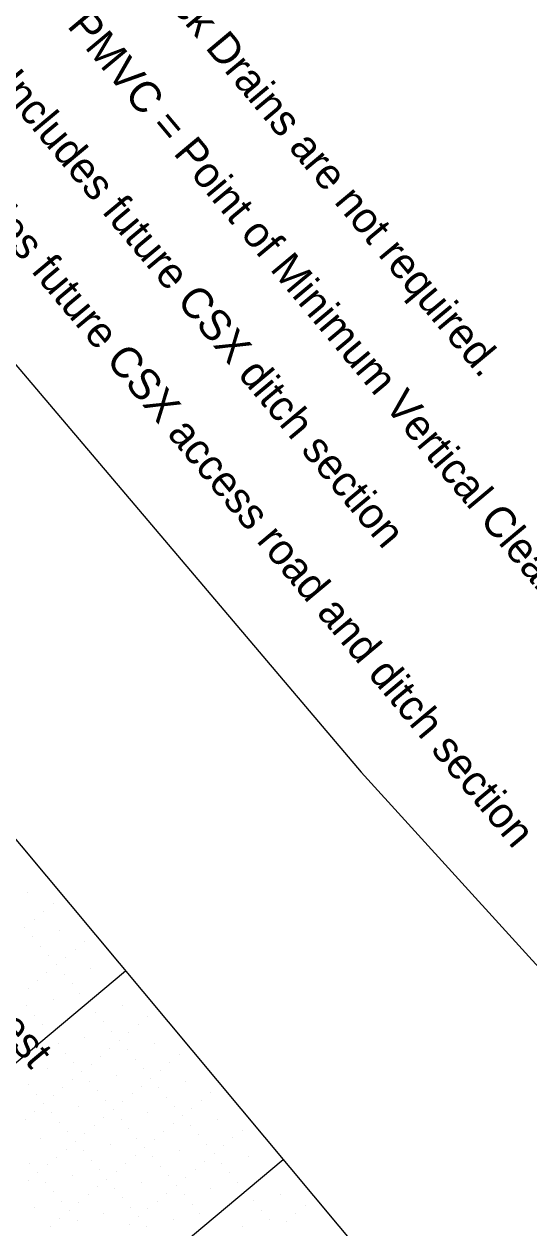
# Model space of a CAD drawing. Extents: x 2042995 to 2043795, y 305365 to 306249.
# Drawn here: x 2043570.9 to 2043611.9, y 305582.4 to 305680.3 of the extents above; entities that cross this region are included whole.
import ezdxf

# ---------------------------------------------------------------- set-up
doc = ezdxf.new("R2010")
doc.units = 0
for name, color, linetype in [('BR_AUTO DIMENSION', 7, 'Continuous'), ('BR_BORDER LINES', 7, 'Continuous'), ('BR_GRID DOTS', 7, 'Continuous'), ('BR_GRID LINES', 7, 'Continuous'), ('BR_GROUND LINES', 7, 'Continuous'), ('BR_TEXT', 7, 'Continuous')]:
    doc.layers.add(name, color=color, linetype=linetype)

msp = doc.modelspace()

# ---------------------------------------------------------------- linework, layer by layer
at = {"layer": 'BR_BORDER LINES'}
msp.add_line((2043183.839, 306076.621), (2043615.462, 305559.826), dxfattribs=at)
at = {"layer": 'BR_GRID DOTS'}
for p, q in [((2043571.193, 305609.711), (2043571.193, 305609.711)), ((2043573.243, 305608.817), (2043573.243, 305608.817)), ((2043571.708, 305607.535), (2043571.708, 305607.535)), ((2043572.475, 305608.176), (2043572.475, 305608.176)), ((2043570.94, 305606.894), (2043570.94, 305606.894)), ((2043573.757, 305606.641), (2043573.757, 305606.641)), ((2043571.581, 305606.126), (2043571.581, 305606.126)), ((2043575.807, 305605.747), (2043575.807, 305605.747)), ((2043572.222, 305605.359), (2043572.222, 305605.359)), ((2043572.863, 305604.591), (2043572.863, 305604.591)), ((2043575.039, 305605.106), (2043575.039, 305605.106)), ((2043573.504, 305603.824), (2043573.504, 305603.824)), ((2043574.272, 305604.465), (2043574.272, 305604.465)), ((2043576.321, 305603.571), (2043576.321, 305603.571)), ((2043571.969, 305602.542), (2043571.969, 305602.542)), ((2043572.737, 305603.183), (2043572.737, 305603.183)), ((2043574.145, 305603.056), (2043574.145, 305603.056)), ((2043571.202, 305601.901), (2043571.202, 305601.901)), ((2043574.786, 305602.289), (2043574.786, 305602.289)), ((2043573.251, 305601.007), (2043573.251, 305601.007)), ((2043575.427, 305601.521), (2043575.427, 305601.521)), ((2043571.075, 305600.492), (2043571.075, 305600.492)), ((2043571.716, 305599.725), (2043571.716, 305599.725)), ((2043576.709, 305599.986), (2043576.709, 305599.986)), ((2043578.885, 305600.501), (2043578.885, 305600.501)), ((2043580.935, 305599.607), (2043580.935, 305599.607)), ((2043572.357, 305598.957), (2043572.357, 305598.957)), ((2043577.35, 305599.219), (2043577.35, 305599.219)), ((2043580.167, 305598.966), (2043580.167, 305598.966)), ((2043575.815, 305597.937), (2043575.815, 305597.937)), ((2043577.991, 305598.451), (2043577.991, 305598.451)), ((2043578.632, 305597.684), (2043578.632, 305597.684)), ((2043579.4, 305598.325), (2043579.4, 305598.325)), ((2043573.639, 305597.422), (2043573.639, 305597.422)), ((2043574.28, 305596.655), (2043574.28, 305596.655)), ((2043577.865, 305597.043), (2043577.865, 305597.043)), ((2043579.273, 305596.916), (2043579.273, 305596.916)), ((2043581.449, 305597.431), (2043581.449, 305597.431)), ((2043574.921, 305595.887), (2043574.921, 305595.887)), ((2043576.33, 305595.761), (2043576.33, 305595.761)), ((2043577.097, 305596.402), (2043577.097, 305596.402)), ((2043579.914, 305596.149), (2043579.914, 305596.149)), ((2043582.732, 305595.896), (2043582.732, 305595.896)), ((2043583.499, 305596.537), (2043583.499, 305596.537)), ((2043572.745, 305595.373), (2043572.745, 305595.373)), ((2043575.562, 305595.12), (2043575.562, 305595.12)), ((2043578.379, 305594.867), (2043578.379, 305594.867)), ((2043580.555, 305595.381), (2043580.555, 305595.381)), ((2043581.964, 305595.255), (2043581.964, 305595.255)), ((2043571.21, 305594.091), (2043571.21, 305594.091)), ((2043574.027, 305593.838), (2043574.027, 305593.838)), ((2043574.795, 305594.479), (2043574.795, 305594.479)), ((2043576.203, 305594.352), (2043576.203, 305594.352)), ((2043580.429, 305593.973), (2043580.429, 305593.973)), ((2043581.196, 305594.614), (2043581.196, 305594.614)), ((2043581.837, 305593.846), (2043581.837, 305593.846)), ((2043584.014, 305594.361), (2043584.014, 305594.361)), ((2043571.851, 305593.323), (2043571.851, 305593.323)), ((2043573.26, 305593.197), (2043573.26, 305593.197)), ((2043576.844, 305593.585), (2043576.844, 305593.585)), ((2043577.485, 305592.817), (2043577.485, 305592.817)), ((2043579.661, 305593.332), (2043579.661, 305593.332)), ((2043582.479, 305593.079), (2043582.479, 305593.079)), ((2043585.296, 305592.826), (2043585.296, 305592.826)), ((2043586.063, 305593.467), (2043586.063, 305593.467)), ((2043571.725, 305591.914), (2043571.725, 305591.914)), ((2043572.492, 305592.556), (2043572.492, 305592.556)), ((2043573.133, 305591.788), (2043573.133, 305591.788)), ((2043575.309, 305592.303), (2043575.309, 305592.303)), ((2043578.126, 305592.05), (2043578.126, 305592.05)), ((2043578.894, 305592.691), (2043578.894, 305592.691)), ((2043580.943, 305591.797), (2043580.943, 305591.797)), ((2043583.12, 305592.311), (2043583.12, 305592.311)), ((2043584.528, 305592.185), (2043584.528, 305592.185)), ((2043570.957, 305591.273), (2043570.957, 305591.273)), ((2043573.774, 305591.02), (2043573.774, 305591.02)), ((2043577.359, 305591.409), (2043577.359, 305591.409)), ((2043578.767, 305591.282), (2043578.767, 305591.282)), ((2043582.993, 305590.903), (2043582.993, 305590.903)), ((2043583.761, 305591.544), (2043583.761, 305591.544)), ((2043586.578, 305591.291), (2043586.578, 305591.291)), ((2043574.415, 305590.253), (2043574.415, 305590.253)), ((2043575.824, 305590.126), (2043575.824, 305590.126)), ((2043576.591, 305590.767), (2043576.591, 305590.767)), ((2043579.408, 305590.515), (2043579.408, 305590.515)), ((2043582.226, 305590.262), (2043582.226, 305590.262)), ((2043584.402, 305590.776), (2043584.402, 305590.776)), ((2043585.043, 305590.009), (2043585.043, 305590.009)), ((2043588.627, 305590.397), (2043588.627, 305590.397)), ((2043572.239, 305589.738), (2043572.239, 305589.738)), ((2043574.289, 305588.844), (2043574.289, 305588.844)), ((2043575.056, 305589.485), (2043575.056, 305589.485)), ((2043577.873, 305589.232), (2043577.873, 305589.232)), ((2043580.049, 305589.747), (2043580.049, 305589.747)), ((2043580.69, 305588.979), (2043580.69, 305588.979)), ((2043581.458, 305589.62), (2043581.458, 305589.62)), ((2043585.684, 305589.241), (2043585.684, 305589.241)), ((2043587.092, 305589.115), (2043587.092, 305589.115)), ((2043587.86, 305589.756), (2043587.86, 305589.756)), ((2043573.521, 305588.203), (2043573.521, 305588.203)), ((2043575.697, 305588.718), (2043575.697, 305588.718)), ((2043576.338, 305587.95), (2043576.338, 305587.95)), ((2043579.923, 305588.338), (2043579.923, 305588.338)), ((2043581.332, 305588.212), (2043581.332, 305588.212)), ((2043583.508, 305588.726), (2043583.508, 305588.726)), ((2043586.325, 305588.473), (2043586.325, 305588.473)), ((2043589.142, 305588.221), (2043589.142, 305588.221)), ((2043571.345, 305587.689), (2043571.345, 305587.689)), ((2043571.986, 305586.921), (2043571.986, 305586.921)), ((2043572.754, 305587.562), (2043572.754, 305587.562)), ((2043576.979, 305587.183), (2043576.979, 305587.183)), ((2043578.388, 305587.056), (2043578.388, 305587.056)), ((2043579.155, 305587.697), (2043579.155, 305587.697)), ((2043581.973, 305587.444), (2043581.973, 305587.444)), ((2043584.79, 305587.191), (2043584.79, 305587.191)), ((2043585.557, 305587.832), (2043585.557, 305587.832)), ((2043586.966, 305587.706), (2043586.966, 305587.706)), ((2043587.607, 305586.938), (2043587.607, 305586.938)), ((2043571.219, 305586.28), (2043571.219, 305586.28)), ((2043572.627, 305586.154), (2043572.627, 305586.154)), ((2043574.803, 305586.668), (2043574.803, 305586.668)), ((2043577.62, 305586.415), (2043577.62, 305586.415)), ((2043580.438, 305586.162), (2043580.438, 305586.162)), ((2043582.614, 305586.677), (2043582.614, 305586.677)), ((2043583.255, 305585.909), (2043583.255, 305585.909)), ((2043584.022, 305586.55), (2043584.022, 305586.55)), ((2043588.248, 305586.171), (2043588.248, 305586.171)), ((2043573.268, 305585.386), (2043573.268, 305585.386)), ((2043576.085, 305585.133), (2043576.085, 305585.133)), ((2043576.853, 305585.774), (2043576.853, 305585.774)), ((2043578.261, 305585.648), (2043578.261, 305585.648)), ((2043582.487, 305585.268), (2043582.487, 305585.268)), ((2043583.896, 305585.142), (2043583.896, 305585.142)), ((2043586.072, 305585.656), (2043586.072, 305585.656)), ((2043591.706, 305585.15), (2043591.706, 305585.15)), ((2043571.733, 305584.104), (2043571.733, 305584.104)), ((2043573.909, 305584.619), (2043573.909, 305584.619)), ((2043575.318, 305584.492), (2043575.318, 305584.492)), ((2043578.902, 305584.88), (2043578.902, 305584.88)), ((2043579.543, 305584.113), (2043579.543, 305584.113)), ((2043580.952, 305583.986), (2043580.952, 305583.986)), ((2043581.72, 305584.627), (2043581.72, 305584.627)), ((2043584.537, 305584.374), (2043584.537, 305584.374)), ((2043589.53, 305584.636), (2043589.53, 305584.636)), ((2043593.755, 305584.256), (2043593.755, 305584.256)), ((2043573.783, 305583.21), (2043573.783, 305583.21)), ((2043574.55, 305583.851), (2043574.55, 305583.851)), ((2043575.191, 305583.084), (2043575.191, 305583.084)), ((2043577.367, 305583.598), (2043577.367, 305583.598)), ((2043580.185, 305583.345), (2043580.185, 305583.345)), ((2043583.002, 305583.092), (2043583.002, 305583.092)), ((2043585.178, 305583.607), (2043585.178, 305583.607)), ((2043590.171, 305583.868), (2043590.171, 305583.868)), ((2043590.812, 305583.101), (2043590.812, 305583.101)), ((2043592.22, 305582.974), (2043592.22, 305582.974)), ((2043592.988, 305583.615), (2043592.988, 305583.615)), ((2043573.015, 305582.569), (2043573.015, 305582.569)), ((2043579.417, 305582.704), (2043579.417, 305582.704)), ((2043580.826, 305582.578), (2043580.826, 305582.578)), ((2043588.636, 305582.586), (2043588.636, 305582.586))]:
    msp.add_line(p, q, dxfattribs=at)
at = {"layer": 'BR_GRID LINES'}
for p, q in [((2043579.138, 305603.318), (2043471.686, 305513.574)), ((2043591.959, 305587.968), (2043484.506, 305498.224))]:
    msp.add_line(p, q, dxfattribs=at)
at = {"layer": 'BR_GROUND LINES'}
for p, q in [((2043565.947, 305657.611), (2043598.291, 305619.48)), ((2043598.291, 305619.48), (2043631.962, 305582.459))]:
    msp.add_line(p, q, dxfattribs=at)

# ---------------------------------------------------------------- texts
at = {"layer": 'BR_AUTO DIMENSION'}
msp.add_text('Minimum Vertical Clearance required, measured from top of high rail to lowest', height=2.5, rotation=309.86836, dxfattribs=at).set_placement((2043497.504, 305683.824))
at = {"layer": 'BR_TEXT'}
for s, p in [('Deck Drains are not required.', (2043580.07, 305684.928)), ('PMVC = Point of Minimum Vertical Clearance', (2043574.314, 305680.12)), ('Includes future CSX ditch section', (2043568.557, 305675.312)), ('Includes future CSX access road and ditch section', (2043562.801, 305670.505))]:
    msp.add_text(s, height=2.5, rotation=309.86836, dxfattribs=at).set_placement(p)

doc.saveas('drawing.dxf')
